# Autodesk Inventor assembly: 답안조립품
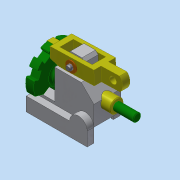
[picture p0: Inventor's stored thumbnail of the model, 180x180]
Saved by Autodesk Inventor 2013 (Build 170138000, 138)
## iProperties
Created: 2016-11
Part Number: 답안조립품
Document SubType Name: Assembly
Designer: dgall
Author: dgall
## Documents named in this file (7)
- C:\Users\dgall\Desktop\461007V1019\461107V1019\답안조립품.iam
- C:\Users\dgall\Desktop\461007V1019\461107V1019\본체.ipt
- C:\Users\dgall\Desktop\461007V1019\461107V1019\부시.ipt
- C:\Users\dgall\Desktop\461007V1019\461107V1019\분할대.ipt
- C:\Users\dgall\Desktop\461007V1019\461107V1019\분할축.ipt
- C:\Users\dgall\Desktop\461007V1019\461107V1019\와셔.ipt
- C:\Users\dgall\Desktop\461007V1019\461107V1019\클레비스핀.ipt
